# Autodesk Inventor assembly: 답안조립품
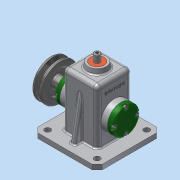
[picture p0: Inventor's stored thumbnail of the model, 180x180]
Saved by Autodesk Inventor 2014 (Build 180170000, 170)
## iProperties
Created: 2016-02
Part Number: 답안조립품
Document SubType Name: Assembly
Designer: SCD-A13
Author: SCD-A13
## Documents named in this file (16)
- C:\Users\SCD-A13\Desktop\460211V1016\답안조립품.iam
- C:\Users\SCD-A13\Desktop\460211V1016\본체.ipt
- C:\Users\SCD-A13\Desktop\460211V1016\V벨트풀리.ipt
- C:\Users\SCD-A13\Desktop\460211V1016\고정핀 1.2 x 10.ipt
- C:\Users\SCD-A13\Desktop\460211V1016\뒤커버.ipt
- C:\Users\SCD-A13\Desktop\460211V1016\링크.ipt
- C:\Users\SCD-A13\Desktop\460211V1016\멈춤나사 M3x8.ipt
- C:\Users\SCD-A13\Desktop\460211V1016\베어링 12 x 32 x 10.ipt
- C:\Users\SCD-A13\Desktop\460211V1016\볼트 M4 x 12.ipt
- C:\Users\SCD-A13\Desktop\460211V1016\부시.ipt
- C:\Users\SCD-A13\Desktop\460211V1016\슬라이드.ipt
- C:\Users\SCD-A13\Desktop\460211V1016\앞커버.ipt
- C:\Users\SCD-A13\Desktop\460211V1016\오일실 12 25 7.ipt
- C:\Users\SCD-A13\Desktop\460211V1016\키 4 x 4 x 10.ipt
- C:\Users\SCD-A13\Desktop\460211V1016\편심축.ipt
- C:\Users\SCD-A13\Desktop\460211V1016\핀 5 x 18.ipt
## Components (11 placed, 4 different names)
1. V벨트풀리:1 — 각도:2
2. 고정핀 1.2 x 10:1 — 각도:3
3. 핀 5 x 18:1 — 각도:3
4. ISO 4762 M4 x 12:1
5. ISO 4762 M4 x 12:2
6. ISO 4762 M4 x 12:3
7. ISO 4762 M4 x 12:4
8. ISO 4762 M4 x 12:5
9. ISO 4762 M4 x 12:6
10. ISO 4762 M4 x 12:7
11. ISO 4762 M4 x 12:8
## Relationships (2: Angle 2)
- 각도:2 [Angle]: V벨트풀리:1
- 각도:3 [Angle]: 고정핀 1.2 x 10:1 ↔ 핀 5 x 18:1
